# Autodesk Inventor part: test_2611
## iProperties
Created: 2004-11
Part Number: test_2611
Cost Center: 0,198 kg
Material: S355 J2G3
Document SubType Name: Blech
Designer: ahuetter
Authority: 25138,06 mm^3
Manufacturer: Standard
Standards Organization: Custom
SaveDate: 2004-11-25
SaveTime: 15:37
TotalMass: 0,198 kg
TotalVolume: 25138,06 mm^3
SM_Thickness: 0,5 mm
SM_Style: Norm
SM_Extents: N/A
Author: ahuetter
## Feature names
1. Extrusion2
2. Wandstärke1
3. Extrusion3
